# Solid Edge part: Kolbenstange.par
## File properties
Username: bmolnar
Dokumentum tartalom típus: 0
Author: bmolnar
Last saved by: bmolnar
Revision: 83
Sűrűség: 0,000 kg/m^3
Pontosság: 0,990
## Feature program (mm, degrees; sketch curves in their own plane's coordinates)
base feature "unnamed BaseFeature 1"
sketch for "unnamed Protrusion 1" plane through (0, 0, -16.4) normal (0, 0, -1) x-axis (0, 1, 0)
  circle centre (0, 0) radius 16
extrude "unnamed Protrusion 1" add finite 18.25 along +normal
sketch for "Kihúzás_2" #1 plane through (0, 0, -16.4) normal (0, 0, -1) x-axis (0, 1, 0)
  circle centre (0, 0) radius 6
sketch for "Kihúzás_2" #2 plane through (0, 0, -16.4) normal (0, 0, -1) x-axis (0, 1, 0)
  circle centre (0, 0) radius 16
extrude "Kihúzás_2" add finite 12.35 along -normal
sketch for "Furat_1" plane through (0, 0, 48.9) normal (0, 0, 1) x-axis (1, 0, 0)
hole "Furat_1" diameter 4.92 finite  VBottomAngle = 118 deg
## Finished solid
Body 1: solid body, 16 faces, 22 edges, 8 vertices.
  Faces by surface: plane 8, cylinder 4, cone 2, torus 2
  Edges by curve: circle 12, line 6, curve on surface 2, ellipse 2
Bounding box of the edges (mm; curved faces can reach further): 32.000 x 32.000 x 86.050, from (-16, -16, -34.65) to (16, 16, 51.4).
Cylindrical faces by radius (mm): R2.46 x1, R3.125 x1, R6 x1, R16 x1
Conical faces (half-angle, radius in mm at the cone's reference point): 45 deg R3.225 x1, 59 deg R2.46 x1
Toroidal faces (ring radius, tube radius in mm): R2.725 r0.4 x1, R4.7 r1.3 x1
Planar faces by outward normal: +x 1, +z 3, -x 1, -z 1, oblique 2
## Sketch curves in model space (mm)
circle centre (0, 0, -16.4) radius 16
circle centre (0, 0, -16.4) radius 6
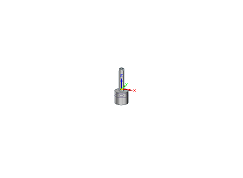
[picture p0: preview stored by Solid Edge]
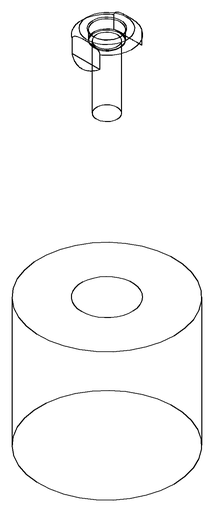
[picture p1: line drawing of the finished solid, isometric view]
